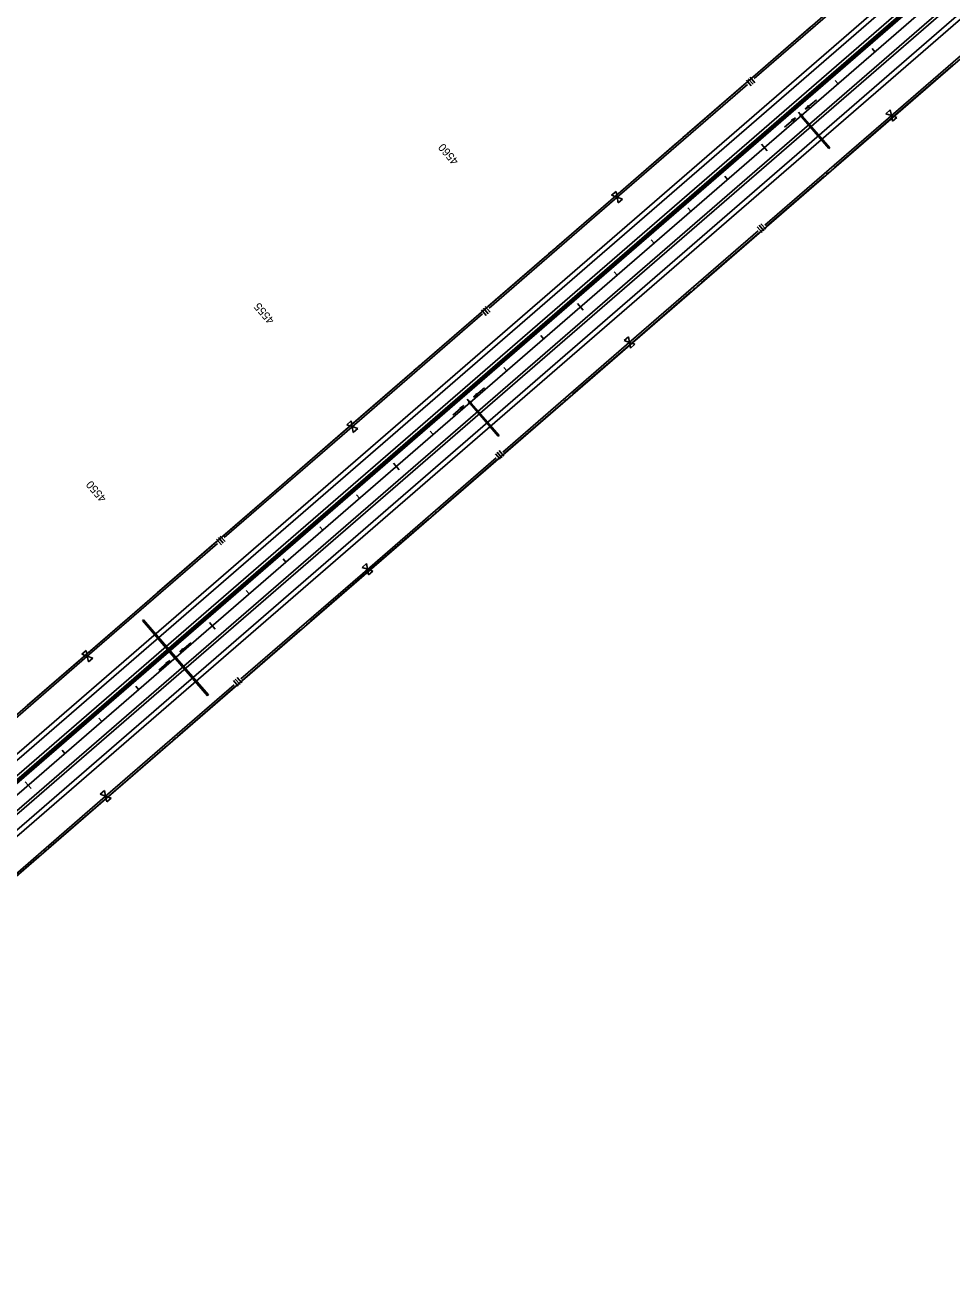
# Model space of a CAD drawing. Extents: x 192699 to 285914, y 194342 to 233219.
# Drawn here: x 204077 to 205979, y 202501 to 205094 of the extents above; entities that cross this region are included whole.
import ezdxf

# ---------------------------------------------------------------- set-up
doc = ezdxf.new("R2010")
doc.units = 0
for name, color, linetype in [('CENT LINE', 7, 'Continuous'), ('CONCRETE', 7, 'Continuous'), ('DRAINAGE', 7, 'Continuous'), ('DRAINAGE ARROWS', 7, 'Continuous'), ('R-W - CofA', 7, 'Continuous'), ('R_Water Annot', 7, 'Continuous'), ('ROAD', 7, 'Continuous'), ('SHOULDER', 7, 'Continuous'), ('STATIONING1', 7, 'Continuous'), ('WRSF', 7, 'Continuous')]:
    doc.layers.add(name, color=color, linetype=linetype)

msp = doc.modelspace()

# ---------------------------------------------------------------- linework, layer by layer
at = {"layer": 'CENT LINE'}
msp.add_line((198833.2, 198989.9), (207514.6, 206505.5), dxfattribs=at)
at = {"layer": 'CONCRETE'}
for p, q in [((203079, 202694.6), (207308.1, 206355.8)), ((203081.6, 202691.6), (207310.6, 206352.7))]:
    msp.add_line(p, q, dxfattribs=at)
at = {"layer": 'DRAINAGE'}
for p, q in [((204317.3, 203872.5), (204382.8, 203796.9)), ((204319.2, 203874.2), (204384.7, 203798.6)), ((204385.4, 203793.9), (204450.9, 203718.3)), ((204387.3, 203795.5), (204452.8, 203719.9))]:
    msp.add_line(p, q, dxfattribs=at)
for points in [[(205670.1, 204906.1), (205673.1, 204908.7), (205670.5, 204911.7), (205667.5, 204909.1)], [(204989.7, 204317), (204992.7, 204319.6), (204990.1, 204322.7), (204987.1, 204320)], [(204384.9, 203793.4), (204387.9, 203796), (204385.3, 203799), (204382.2, 203796.4)]]:
    msp.add_lwpolyline(points, close=True, dxfattribs=at)
for points in [[(205670.9, 204906.7), (205727.2, 204841.7)], [(205672.4, 204908.1), (205728.7, 204843)], [(205727.2, 204841.7), (205728.7, 204843)], [(204990.4, 204317.7), (205048, 204251.1)], [(204992, 204319), (205049.6, 204252.5)], [(205049.6, 204252.5), (205048, 204251.1)], [(204317.3, 203872.5), (204319.2, 203874.2)], [(204452.8, 203719.9), (204450.9, 203718.3)]]:
    msp.add_lwpolyline(points, dxfattribs=at)
at = {"layer": 'DRAINAGE ARROWS'}
for p, q in [((205685.2, 204929.6), (205678.6, 204921.9)), ((205687.2, 204927.3), (205678.6, 204921.9)), ((205685.4, 204929.4), (205679.9, 204923)), ((205687, 204927.5), (205679.9, 204923)), ((205685.5, 204929.2), (205681.2, 204924.1)), ((205686.8, 204927.7), (205681.2, 204924.1)), ((205685.7, 204929), (205682.5, 204925.2)), ((205686.7, 204927.9), (205682.5, 204925.2)), ((205685.9, 204928.8), (205683.7, 204926.3)), ((205686.5, 204928.1), (205683.7, 204926.3)), ((205686, 204928.6), (205685, 204927.4)), ((205686.3, 204928.3), (205685, 204927.4)), ((205687.2, 204927.3), (205685.2, 204929.6)), ((205650.2, 204899.3), (205658.7, 204904.7)), ((205652.1, 204897), (205650.2, 204899.3)), ((205650.4, 204899.1), (205657.5, 204903.6)), ((205650.5, 204898.9), (205656.2, 204902.5)), ((205650.7, 204898.7), (205654.9, 204901.4)), ((205650.8, 204898.5), (205653.6, 204900.3)), ((205651, 204898.3), (205652.4, 204899.2)), ((205651.3, 204898), (205652.4, 204899.2)), ((205651.5, 204897.8), (205653.6, 204900.3)), ((205651.7, 204897.6), (205654.9, 204901.4)), ((205651.8, 204897.4), (205656.2, 204902.5)), ((205652, 204897.2), (205657.5, 204903.6)), ((205652.1, 204897), (205658.7, 204904.7)), ((205003.8, 204338.5), (204997.3, 204330.9)), ((205005.8, 204336.3), (204997.3, 204330.9)), ((205004, 204338.4), (204998.5, 204331.9)), ((205005.6, 204336.5), (204998.5, 204331.9)), ((205004.2, 204338.2), (204999.8, 204333.1)), ((205005.5, 204336.7), (204999.8, 204333.1)), ((205004.3, 204338), (205001.1, 204334.2)), ((205005.3, 204336.9), (205001.1, 204334.2)), ((205004.5, 204337.8), (205002.4, 204335.3)), ((205005.1, 204337), (205002.4, 204335.3)), ((205004.7, 204337.6), (205003.6, 204336.4)), ((205005, 204337.2), (205003.6, 204336.4)), ((205005.8, 204336.3), (205003.8, 204338.5)), ((204968.8, 204308.2), (204977.4, 204313.6)), ((204970.8, 204306), (204968.8, 204308.2)), ((204969, 204308), (204976.1, 204312.5)), ((204969.1, 204307.9), (204974.8, 204311.4)), ((204969.3, 204307.7), (204973.5, 204310.3)), ((204969.5, 204307.5), (204972.3, 204309.2)), ((204969.6, 204307.3), (204971, 204308.1)), ((204970, 204306.9), (204971, 204308.1)), ((204970.1, 204306.7), (204972.3, 204309.2)), ((204970.3, 204306.5), (204973.5, 204310.3)), ((204970.4, 204306.3), (204974.8, 204311.4)), ((204970.6, 204306.2), (204976.1, 204312.5)), ((204970.8, 204306), (204977.4, 204313.6)), ((204400.4, 203815.1), (204393.8, 203807.4)), ((204402.3, 203812.8), (204393.8, 203807.4)), ((204400.5, 203814.9), (204395.1, 203808.5)), ((204402.2, 203813), (204395.1, 203808.5)), ((204400.7, 203814.7), (204396.4, 203809.6)), ((204402, 203813.2), (204396.4, 203809.6)), ((204400.9, 203814.5), (204397.6, 203810.7)), ((204401.8, 203813.4), (204397.6, 203810.7)), ((204401, 203814.3), (204398.9, 203811.8)), ((204401.7, 203813.6), (204398.9, 203811.8)), ((204401.2, 203814.1), (204400.2, 203812.9)), ((204401.5, 203813.8), (204400.2, 203812.9)), ((204402.3, 203812.8), (204400.4, 203815.1)), ((204365.4, 203784.8), (204373.9, 203790.2)), ((204367.3, 203782.5), (204365.4, 203784.8)), ((204365.5, 203784.6), (204372.6, 203789.1)), ((204365.7, 203784.4), (204371.3, 203788)), ((204365.8, 203784.2), (204370.1, 203786.9)), ((204366, 203784), (204368.8, 203785.8)), ((204366.2, 203783.8), (204367.5, 203784.7)), ((204366.5, 203783.5), (204367.5, 203784.7)), ((204366.7, 203783.3), (204368.8, 203785.8)), ((204366.8, 203783.1), (204370.1, 203786.9)), ((204367, 203782.9), (204371.3, 203788)), ((204367.2, 203782.7), (204372.6, 203789.1)), ((204367.3, 203782.5), (204373.9, 203790.2))]:
    msp.add_line(p, q, dxfattribs=at)
at = {"layer": 'R-W - CofA'}
for p, q in [((205557.6, 204981.4), (205567.6, 204969.9)), ((205561.5, 204984.7), (205571.4, 204973.2)), ((205565.3, 204988), (205575.2, 204976.5)), ((205844.2, 204912.9), (205853.2, 204920.7)), ((205855.4, 204909.1), (205844.2, 204912.9)), ((205853.2, 204920.7), (205855.4, 204909.1)), ((205857.6, 204897.5), (205855.4, 204909.1)), ((205855.4, 204909.1), (205866.5, 204905.2)), ((205866.5, 204905.2), (205857.6, 204897.5)), ((205280.9, 204745.4), (205289.9, 204753.2)), ((205292.2, 204741.5), (205280.9, 204745.4)), ((205289.9, 204753.2), (205292.2, 204741.5)), ((205294.4, 204729.8), (205292.2, 204741.5)), ((205292.2, 204741.5), (205303.4, 204737.6)), ((205303.4, 204737.6), (205294.4, 204729.8)), ((205580, 204680.6), (205589.8, 204669.2)), ((205583.7, 204683.9), (205593.6, 204672.5)), ((205587.5, 204687.1), (205597.4, 204675.8)), ((205013.6, 204510.4), (205023.5, 204498.9)), ((205017.4, 204513.7), (205027.4, 204502.2)), ((205021.3, 204517), (205031.2, 204505.5)), ((205306.3, 204447.3), (205315.3, 204455)), ((205315.3, 204455), (205317.5, 204443.4)), ((205317.5, 204443.4), (205306.3, 204447.3)), ((205319.7, 204431.8), (205317.5, 204443.4)), ((205317.5, 204443.4), (205328.6, 204439.5)), ((205328.6, 204439.5), (205319.7, 204431.8)), ((204736.8, 204274.4), (204745.9, 204282.2)), ((204748.1, 204270.5), (204736.8, 204274.4)), ((204745.9, 204282.2), (204748.1, 204270.5)), ((204750.4, 204258.8), (204748.1, 204270.5)), ((204748.1, 204270.5), (204759.4, 204266.6)), ((204759.4, 204266.6), (204750.4, 204258.8)), ((205049.6, 204221.4), (205059.5, 204210.1)), ((205042.1, 204214.9), (205051.9, 204203.5)), ((205045.8, 204218.2), (205055.7, 204206.8)), ((204469.5, 204039.4), (204479.5, 204027.9)), ((204473.4, 204042.7), (204483.3, 204031.2)), ((204477.2, 204046), (204487.1, 204034.5)), ((204768.4, 203981.6), (204777.3, 203989.3)), ((204777.3, 203989.3), (204779.6, 203977.7)), ((204779.6, 203977.7), (204768.4, 203981.6)), ((204781.8, 203966.1), (204779.6, 203977.7)), ((204779.6, 203977.7), (204790.7, 203973.9)), ((204790.7, 203973.9), (204781.8, 203966.1)), ((204192.8, 203803.4), (204201.8, 203811.2)), ((204201.8, 203811.2), (204204.1, 203799.5)), ((204204.1, 203799.5), (204192.8, 203803.4)), ((204206.3, 203787.8), (204204.1, 203799.5)), ((204204.1, 203799.5), (204215.3, 203795.6)), ((204215.3, 203795.6), (204206.3, 203787.8)), ((204511.7, 203755.8), (204521.5, 203744.4)), ((204504.1, 203749.2), (204514, 203737.9)), ((204507.9, 203752.5), (204517.8, 203741.1)), ((204230.5, 203515.9), (204239.4, 203523.6)), ((204239.4, 203523.6), (204241.7, 203512)), ((204241.7, 203512), (204230.5, 203515.9)), ((204243.9, 203500.5), (204241.7, 203512)), ((204241.7, 203512), (204252.8, 203508.2)), ((204252.8, 203508.2), (204243.9, 203500.5))]:
    msp.add_line(p, q, dxfattribs=at)
for points in [[(203774, 203432.6), (206042.1, 205396.1), (206259.1, 205603.8), (207302.5, 206507.1)], [(203710.8, 203047.2), (206205.8, 205207.1), (206442.4, 205392.1), (207485.7, 206295.4)], [(205573.3, 204984.9), (205840.7, 205216.4)], [(205859.9, 204912.9), (206119.8, 205138)], [(205570.7, 204988), (205691.6, 205092.7)], [(205862.5, 204909.9), (205982, 205013.4)], [(205296.7, 204745.4), (205559.6, 204973)], [(205436, 204871.4), (205556.9, 204976.1)], [(205595.5, 204684.1), (205859.9, 204912.9)], [(205738.4, 204802.5), (205862.5, 204909.9)], [(205294, 204748.5), (205415, 204853.2)], [(205418.9, 204856.5), (205423.5, 204860.6)], [(205427.4, 204863.9), (205432.1, 204868)], [(205721.5, 204787.9), (205726.1, 204791.9)], [(205730, 204795.2), (205734.6, 204799.2)], [(205598.1, 204681), (205717.7, 204784.6)], [(205029.3, 204513.9), (205296.7, 204745.4)], [(205168.6, 204639.9), (205294, 204748.5)], [(205321.9, 204447.3), (205581.9, 204672.3)], [(205464.9, 204565.7), (205584.5, 204669.2)], [(205160, 204632.5), (205164.7, 204636.5)], [(205026.6, 204517), (205147.6, 204621.7)], [(205151.5, 204625.1), (205156.1, 204629.1)], [(205456.4, 204558.4), (205461.1, 204562.4)], [(205324.6, 204444.2), (205444.1, 204547.8)], [(205448, 204551.1), (205452.6, 204555.1)], [(204752.6, 204274.4), (205015.5, 204502)], [(204891.9, 204400.4), (205012.9, 204505.1)], [(205057.6, 204218.4), (205321.9, 204447.3)], [(205200.5, 204336.9), (205324.6, 204444.2)], [(204750, 204277.5), (204870.9, 204382.2)], [(204874.8, 204385.5), (204879.5, 204389.6)], [(204883.4, 204393), (204888, 204397)], [(205183.6, 204322.2), (205188.2, 204326.2)], [(205192.1, 204329.5), (205196.7, 204333.5)], [(205060.2, 204215.4), (205179.8, 204318.9)], [(204485.2, 204042.9), (204752.6, 204274.4)], [(204624.5, 204168.9), (204750, 204277.5)], [(204784, 203981.6), (205043.9, 204206.6)], [(204927, 204100), (205046.6, 204203.6)], [(204482.6, 204046), (204603.5, 204150.7)], [(204607.4, 204154.1), (204612.1, 204158.1)], [(204616, 204161.5), (204620.6, 204165.5)], [(204918.5, 204092.7), (204923.1, 204096.7)], [(204786.6, 203978.6), (204906.2, 204082.1)], [(204910.1, 204085.4), (204914.7, 204089.4)], [(204208.6, 203803.4), (204471.5, 204031)], [(204347.9, 203929.4), (204468.8, 204034.1)], [(204519.7, 203752.7), (204784, 203981.6)], [(204662.6, 203871.2), (204786.6, 203978.6)], [(204205.9, 203806.5), (204326.9, 203911.2)], [(204330.8, 203914.5), (204335.4, 203918.6)], [(204339.3, 203922), (204344, 203926)], [(204645.7, 203856.5), (204650.3, 203860.5)], [(204654.2, 203863.9), (204658.8, 203867.8)], [(204522.3, 203749.7), (204641.8, 203853.2)], [(204080.5, 203697.9), (204205.9, 203806.5)], [(203941.2, 203571.9), (204208.6, 203803.4)], [(204246.1, 203515.9), (204506, 203740.9)], [(204389.1, 203634.4), (204508.6, 203737.9)], [(204380.6, 203627), (204385.2, 203631)], [(204248.7, 203512.9), (204368.3, 203616.4)], [(204372.2, 203619.7), (204376.8, 203623.7)], [(203981.7, 203287), (204246.1, 203515.9)], [(204124.7, 203405.5), (204248.7, 203512.9)], [(204107.8, 203390.8), (204112.4, 203394.8)], [(204116.2, 203398.2), (204120.9, 203402.2)], [(203984.4, 203284), (204103.9, 203387.5)]]:
    msp.add_lwpolyline(points, dxfattribs=at)
at = {"layer": 'R_Water Annot'}
for p, q in [((205701.3, 204941.6), (205678.6, 204921.9)), ((205685.2, 204929.6), (205678.6, 204921.9)), ((205687.2, 204927.3), (205678.6, 204921.9)), ((205685.4, 204929.4), (205679.9, 204923)), ((205687, 204927.5), (205679.9, 204923)), ((205685.5, 204929.2), (205681.2, 204924.1)), ((205686.8, 204927.7), (205681.2, 204924.1)), ((205685.7, 204929), (205682.5, 204925.2)), ((205686.7, 204927.9), (205682.5, 204925.2)), ((205685.9, 204928.8), (205683.7, 204926.3)), ((205686.5, 204928.1), (205683.7, 204926.3)), ((205686, 204928.6), (205685, 204927.4)), ((205686.3, 204928.3), (205685, 204927.4)), ((205687.2, 204927.3), (205685.2, 204929.6)), ((205636, 204885.1), (205658.7, 204904.7)), ((205650.2, 204899.3), (205658.7, 204904.7)), ((205652.1, 204897), (205650.2, 204899.3)), ((205650.4, 204899.1), (205657.5, 204903.6)), ((205650.5, 204898.9), (205656.2, 204902.5)), ((205650.7, 204898.7), (205654.9, 204901.4)), ((205650.8, 204898.5), (205653.6, 204900.3)), ((205651, 204898.3), (205652.4, 204899.2)), ((205651.3, 204898), (205652.4, 204899.2)), ((205651.5, 204897.8), (205653.6, 204900.3)), ((205651.7, 204897.6), (205654.9, 204901.4)), ((205651.8, 204897.4), (205656.2, 204902.5)), ((205652, 204897.2), (205657.5, 204903.6)), ((205652.1, 204897), (205658.7, 204904.7)), ((205019.9, 204350.5), (204997.3, 204330.9)), ((205003.8, 204338.5), (204997.3, 204330.9)), ((205005.8, 204336.3), (204997.3, 204330.9)), ((205004, 204338.4), (204998.5, 204331.9)), ((205005.6, 204336.5), (204998.5, 204331.9)), ((205004.2, 204338.2), (204999.8, 204333.1)), ((205005.5, 204336.7), (204999.8, 204333.1)), ((205004.3, 204338), (205001.1, 204334.2)), ((205005.3, 204336.9), (205001.1, 204334.2)), ((205004.5, 204337.8), (205002.4, 204335.3)), ((205005.1, 204337), (205002.4, 204335.3)), ((205004.7, 204337.6), (205003.6, 204336.4)), ((205005, 204337.2), (205003.6, 204336.4)), ((205005.8, 204336.3), (205003.8, 204338.5)), ((204954.6, 204294), (204977.4, 204313.6)), ((204968.8, 204308.2), (204977.4, 204313.6)), ((204970.8, 204306), (204968.8, 204308.2)), ((204969, 204308), (204976.1, 204312.5)), ((204969.1, 204307.9), (204974.8, 204311.4)), ((204969.3, 204307.7), (204973.5, 204310.3)), ((204969.5, 204307.5), (204972.3, 204309.2)), ((204969.6, 204307.3), (204971, 204308.1)), ((204970, 204306.9), (204971, 204308.1)), ((204970.1, 204306.7), (204972.3, 204309.2)), ((204970.3, 204306.5), (204973.5, 204310.3)), ((204970.4, 204306.3), (204974.8, 204311.4)), ((204970.6, 204306.2), (204976.1, 204312.5)), ((204970.8, 204306), (204977.4, 204313.6)), ((204416.4, 203827.1), (204393.8, 203807.4)), ((204400.4, 203815.1), (204393.8, 203807.4)), ((204402.3, 203812.8), (204393.8, 203807.4)), ((204400.5, 203814.9), (204395.1, 203808.5)), ((204402.2, 203813), (204395.1, 203808.5)), ((204400.7, 203814.7), (204396.4, 203809.6)), ((204402, 203813.2), (204396.4, 203809.6)), ((204400.9, 203814.5), (204397.6, 203810.7)), ((204401.8, 203813.4), (204397.6, 203810.7)), ((204401, 203814.3), (204398.9, 203811.8)), ((204401.7, 203813.6), (204398.9, 203811.8)), ((204401.2, 203814.1), (204400.2, 203812.9)), ((204401.5, 203813.8), (204400.2, 203812.9)), ((204402.3, 203812.8), (204400.4, 203815.1)), ((204351.2, 203770.6), (204373.9, 203790.2)), ((204365.4, 203784.8), (204373.9, 203790.2)), ((204367.3, 203782.5), (204365.4, 203784.8)), ((204365.5, 203784.6), (204372.6, 203789.1)), ((204365.7, 203784.4), (204371.3, 203788)), ((204365.8, 203784.2), (204370.1, 203786.9)), ((204366, 203784), (204368.8, 203785.8)), ((204366.2, 203783.8), (204367.5, 203784.7)), ((204366.5, 203783.5), (204367.5, 203784.7)), ((204366.7, 203783.3), (204368.8, 203785.8)), ((204366.8, 203783.1), (204370.1, 203786.9)), ((204367, 203782.9), (204371.3, 203788)), ((204367.2, 203782.7), (204372.6, 203789.1)), ((204367.3, 203782.5), (204373.9, 203790.2))]:
    msp.add_line(p, q, dxfattribs=at)
at = {"layer": 'ROAD'}
for p, q in [((198797.8, 199030.7), (207479.2, 206546.3)), ((198813.5, 199012.5), (207494.9, 206528.2)), ((198852.8, 198967.2), (207534.2, 206482.8)), ((198868.5, 198949), (207549.9, 206464.7))]:
    msp.add_line(p, q, dxfattribs=at)
at = {"layer": 'SHOULDER'}
for p, q in [((203018.9, 202698.1), (207472.7, 206553.9)), ((203077.6, 202696.1), (207498.9, 206523.7)), ((203109.1, 202659.8), (207530.3, 206487.4)), ((203088.4, 202589), (207556.5, 206457.1))]:
    msp.add_line(p, q, dxfattribs=at)
at = {"layer": 'STATIONING1'}
for points in [[(205815.6, 205046.6), (205821.5, 205039.8)], [(205740, 204981.2), (205745.9, 204974.4)], [(205664.4, 204915.7), (205670.3, 204908.9)], [(205588.8, 204850.3), (205600.6, 204836.7)], [(205513.2, 204784.8), (205519.1, 204778)], [(205437.6, 204719.4), (205443.5, 204712.6)], [(205362, 204653.9), (205367.9, 204647.1)], [(205286.4, 204588.5), (205292.3, 204581.6)], [(205210.8, 204523), (205222.6, 204509.4)], [(205135.2, 204457.5), (205141.1, 204450.7)], [(205059.6, 204392.1), (205065.5, 204385.3)], [(204984, 204326.6), (204989.9, 204319.8)], [(204908.4, 204261.2), (204914.3, 204254.4)], [(204832.8, 204195.7), (204844.6, 204182.1)], [(204757.2, 204130.3), (204763.1, 204123.5)], [(204681.6, 204064.8), (204687.5, 204058)], [(204606, 203999.4), (204611.9, 203992.6)], [(204530.4, 203933.9), (204536.3, 203927.1)], [(204454.8, 203868.5), (204466.6, 203854.9)], [(204379.2, 203803), (204385.1, 203796.2)], [(204303.6, 203737.6), (204309.5, 203730.8)], [(204228, 203672.1), (204233.8, 203665.3)], [(204152.4, 203606.7), (204158.2, 203599.9)], [(204076.7, 203541.2), (204088.5, 203527.6)]]:
    msp.add_lwpolyline(points, dxfattribs=at)
at = {"layer": 'WRSF'}
msp.add_line((203046.3, 202663.7), (207309.3, 206354.3), dxfattribs=at)

# ---------------------------------------------------------------- texts
at = {"layer": 'STATIONING1'}
for s, p in [('4560', (204967.8, 204816.3)), ('4555', (204589.4, 204489.5)), ('4550', (204244.5, 204124.1))]:
    msp.add_text(s, height=16.5, rotation=130.8833, dxfattribs=at).set_placement(p)

doc.saveas('drawing.dxf')
